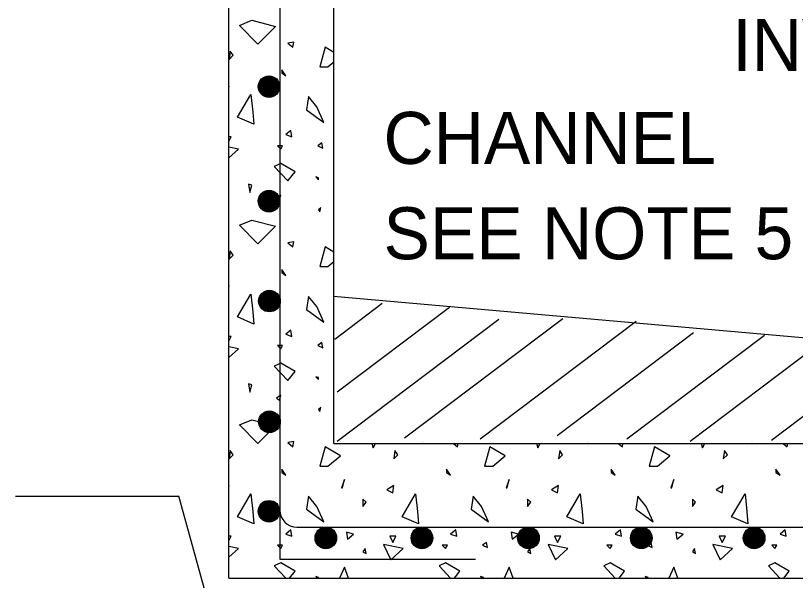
# Model space of a CAD drawing. Extents: x 5.8 to 18, y -5.2 to 5.4.
# Drawn here: x 11.214 to 12.113, y -2.201 to -1.55 of the extents above; entities that cross this region are included whole.
import ezdxf

# ---------------------------------------------------------------- set-up
doc = ezdxf.new("R2010")
doc.units = 0
for name, color, linetype in [('DETL-DIMS', 7, 'Continuous'), ('DETL-LINE', 7, 'Continuous'), ('DETL-NOTE', 7, 'Continuous'), ('DETL-PATT', 7, 'Continuous')]:
    doc.layers.add(name, color=color, linetype=linetype)

msp = doc.modelspace()

# ---------------------------------------------------------------- linework, layer by layer
at = {"layer": 'DETL-DIMS'}
for p in [(11.21361, -2.10408), (11.46459, -2.33018)]:
    msp.add_line(p, (11.40182, -2.10408), dxfattribs=at)
at = {"layer": 'DETL-LINE'}
for p, q in [((11.45961, -2.19861), (11.45961, -0.69269)), ((11.5809, -2.04328), (11.5809, -0.81414)), ((11.51843, -1.37418), (11.51843, -2.1203)), ((12.51612, -1.95637), (11.58024, -1.87386)), ((11.5809, -2.04328), (12.51612, -2.04328)), ((11.51843, -2.1203), (11.51843, -2.17673)), ((11.53804, -2.1399), (12.55565, -2.1399)), ((11.51843, -2.17673), (11.744, -2.17673)), ((11.45961, -2.19861), (12.646, -2.19861))]:
    msp.add_line(p, q, dxfattribs=at)
for centre, radius in [((11.50597, -1.63175), 0.01247), ((11.50586, -1.63164), 0.01163), ((11.50474, -1.63164), 0.01009), ((11.506, -1.63194), 0.01122), ((11.50633, -1.63247), 0.011), ((11.50627, -1.63207), 0.01024), ((11.50515, -1.63115), 0.00834), ((11.50655, -1.63213), 0.00969), ((11.50662, -1.63241), 0.00918), ((11.50496, -1.63213), 0.00724), ((11.50676, -1.63254), 0.00876), ((11.50662, -1.63276), 0.00835), ((11.50433, -1.63254), 0.00578), ((11.50684, -1.63276), 0.00814), ((11.50668, -1.63262), 0.00786), ((11.50704, -1.63282), 0.00751), ((11.50711, -1.63268), 0.00704), ((11.50717, -1.6326), 0.00655), ((11.50529, -1.63227), 0.00467), ((11.50717, -1.63247), 0.006), ((11.50725, -1.63262), 0.00565), ((11.50725, -1.63268), 0.0051), ((11.50747, -1.63311), 0.00488), ((11.50758, -1.63317), 0.00445), ((11.50758, -1.63305), 0.0039), ((11.50774, -1.63296), 0.00377), ((11.50774, -1.63331), 0.00347), ((11.50788, -1.63303), 0.00333), ((11.50794, -1.63311), 0.00285), ((11.50774, -1.6329), 0.00238), ((11.50802, -1.63319), 0.00212), ((11.50809, -1.63317), 0.00175), ((11.50823, -1.63325), 0.00133), ((11.50823, -1.63311), 0.00118), ((11.50864, -1.63317), 0.00148), ((11.50821, -1.63311), 0.000769), ((11.50807, -1.63311), 0.000362), ((11.50837, -1.63311), 0.00023), ((11.50597, -1.76383), 0.01247), ((11.50586, -1.76372), 0.01163), ((11.50474, -1.76372), 0.01009), ((11.506, -1.76402), 0.01122), ((11.50633, -1.76454), 0.011), ((11.50627, -1.76415), 0.01024), ((11.50515, -1.76323), 0.00834), ((11.50655, -1.76421), 0.00969), ((11.50662, -1.76449), 0.00918), ((11.50496, -1.76421), 0.00724), ((11.50676, -1.76462), 0.00876), ((11.50662, -1.76484), 0.00835), ((11.50433, -1.76462), 0.00578), ((11.50684, -1.76484), 0.00814), ((11.50668, -1.7647), 0.00786), ((11.50704, -1.7649), 0.00751), ((11.50711, -1.76476), 0.00704), ((11.50717, -1.76468), 0.00655), ((11.50529, -1.76435), 0.00467), ((11.50717, -1.76454), 0.006), ((11.50725, -1.7647), 0.00565), ((11.50725, -1.76476), 0.0051), ((11.50747, -1.76519), 0.00488), ((11.50758, -1.76525), 0.00445), ((11.50758, -1.76513), 0.0039), ((11.50774, -1.76503), 0.00377), ((11.50774, -1.76539), 0.00347), ((11.50788, -1.76511), 0.00333), ((11.50794, -1.76519), 0.00285), ((11.50774, -1.76498), 0.00238), ((11.50802, -1.76527), 0.00212), ((11.50809, -1.76525), 0.00175), ((11.50823, -1.76533), 0.00133), ((11.50823, -1.76519), 0.00118), ((11.50864, -1.76525), 0.00148), ((11.50821, -1.76519), 0.000769), ((11.50807, -1.76519), 0.000362), ((11.50837, -1.76519), 0.00023), ((11.50644, -1.87909), 0.01247), ((11.50633, -1.87898), 0.01163), ((11.50522, -1.87898), 0.01009), ((11.50647, -1.87928), 0.01122), ((11.5068, -1.87981), 0.011), ((11.50675, -1.87941), 0.01024), ((11.50563, -1.87849), 0.00834), ((11.50702, -1.87947), 0.00969), ((11.5071, -1.87975), 0.00918), ((11.50724, -1.87988), 0.00876), ((11.50543, -1.87947), 0.00724), ((11.5071, -1.8801), 0.00835), ((11.5048, -1.87988), 0.00578), ((11.50731, -1.8801), 0.00814), ((11.50716, -1.87996), 0.00786), ((11.50751, -1.88016), 0.00751), ((11.50759, -1.88002), 0.00704), ((11.50576, -1.87961), 0.00467), ((11.50765, -1.87994), 0.00655), ((11.50765, -1.87981), 0.006), ((11.50773, -1.87996), 0.00565), ((11.50773, -1.88002), 0.0051), ((11.50794, -1.88045), 0.00488), ((11.50806, -1.88051), 0.00445), ((11.50806, -1.88039), 0.0039), ((11.50822, -1.8803), 0.00377), ((11.50822, -1.88065), 0.00347), ((11.50835, -1.88037), 0.00333), ((11.50841, -1.88045), 0.00285), ((11.50822, -1.88024), 0.00238), ((11.50849, -1.88053), 0.00212), ((11.50857, -1.88051), 0.00175), ((11.50871, -1.88059), 0.00133), ((11.50871, -1.88045), 0.00118), ((11.50912, -1.88051), 0.00148), ((11.50869, -1.88045), 0.000769), ((11.50855, -1.88045), 0.000362), ((11.50884, -1.88045), 0.00023), ((11.50644, -2.01834), 0.01247), ((11.50633, -2.01824), 0.01163), ((11.50522, -2.01824), 0.01009), ((11.50647, -2.01853), 0.01122), ((11.5068, -2.01906), 0.011), ((11.50675, -2.01867), 0.01024), ((11.50563, -2.01775), 0.00834), ((11.50702, -2.01873), 0.00969), ((11.5071, -2.019), 0.00918), ((11.50543, -2.01873), 0.00724), ((11.50724, -2.01914), 0.00876), ((11.5071, -2.01935), 0.00835), ((11.5048, -2.01914), 0.00578), ((11.50731, -2.01935), 0.00814), ((11.50716, -2.01922), 0.00786), ((11.50751, -2.01941), 0.00751), ((11.50759, -2.01928), 0.00704), ((11.50576, -2.01886), 0.00467), ((11.50765, -2.0192), 0.00655), ((11.50765, -2.01906), 0.006), ((11.50773, -2.01922), 0.00565), ((11.50773, -2.01928), 0.0051), ((11.50794, -2.01971), 0.00488), ((11.50806, -2.01977), 0.00445), ((11.50806, -2.01965), 0.0039), ((11.50822, -2.01955), 0.00377), ((11.50822, -2.0199), 0.00347), ((11.50835, -2.01963), 0.00333), ((11.50841, -2.01971), 0.00285), ((11.50822, -2.01949), 0.00238), ((11.50849, -2.01979), 0.00212), ((11.50857, -2.01977), 0.00175), ((11.50871, -2.01985), 0.00133), ((11.50871, -2.01971), 0.00118), ((11.50912, -2.01977), 0.00148), ((11.50869, -2.01971), 0.000769), ((11.50855, -2.01971), 0.000362), ((11.50884, -2.01971), 0.00023), ((11.50597, -2.12159), 0.01247), ((11.50586, -2.12149), 0.01163), ((11.50474, -2.12149), 0.01009), ((11.506, -2.12178), 0.01122), ((11.50633, -2.12231), 0.011), ((11.50627, -2.12192), 0.01024), ((11.50515, -2.121), 0.00834), ((11.50655, -2.12198), 0.00969), ((11.50662, -2.12225), 0.00918), ((11.50676, -2.12239), 0.00876), ((11.50496, -2.12198), 0.00724), ((11.50662, -2.1226), 0.00835), ((11.50433, -2.12239), 0.00578), ((11.50684, -2.1226), 0.00814), ((11.50668, -2.12247), 0.00786), ((11.50704, -2.12266), 0.00751), ((11.50711, -2.12252), 0.00704), ((11.50717, -2.12245), 0.00655), ((11.50529, -2.12211), 0.00467), ((11.50717, -2.12231), 0.006), ((11.50725, -2.12247), 0.00565), ((11.50725, -2.12252), 0.0051), ((11.50747, -2.12296), 0.00488), ((11.50758, -2.12302), 0.00445), ((11.50758, -2.1229), 0.0039), ((11.50774, -2.1228), 0.00377), ((11.50774, -2.12315), 0.00347), ((11.50788, -2.12288), 0.00333), ((11.50794, -2.12296), 0.00285), ((11.50774, -2.12274), 0.00238), ((11.50802, -2.12303), 0.00212), ((11.50809, -2.12302), 0.00175), ((11.50823, -2.12309), 0.00133), ((11.50823, -2.12296), 0.00118), ((11.50864, -2.12302), 0.00148), ((11.50821, -2.12296), 0.000769), ((11.50807, -2.12296), 0.000362), ((11.50837, -2.12296), 0.00023), ((11.57149, -2.15237), 0.01247), ((11.57138, -2.15227), 0.01163), ((11.68235, -2.15237), 0.01247), ((11.68225, -2.15227), 0.01163), ((11.80525, -2.15237), 0.01247), ((11.80515, -2.15227), 0.01163), ((11.93541, -2.15237), 0.01247), ((11.93531, -2.15227), 0.01163), ((12.06557, -2.15237), 0.01247), ((12.06546, -2.15227), 0.01163), ((11.57027, -2.15227), 0.01009), ((11.57152, -2.15256), 0.01122), ((11.57185, -2.15309), 0.011), ((11.5718, -2.1527), 0.01024), ((11.57068, -2.15178), 0.00834), ((11.57207, -2.15276), 0.00969), ((11.57215, -2.15303), 0.00918), ((11.57048, -2.15276), 0.00724), ((11.57229, -2.15317), 0.00876), ((11.57215, -2.15338), 0.00835), ((11.56985, -2.15317), 0.00578), ((11.57236, -2.15338), 0.00814), ((11.57221, -2.15325), 0.00786), ((11.57256, -2.15344), 0.00751), ((11.57264, -2.1533), 0.00704), ((11.57081, -2.15289), 0.00467), ((11.5727, -2.15323), 0.00655), ((11.5727, -2.15309), 0.006), ((11.57278, -2.15325), 0.00565), ((11.57278, -2.1533), 0.0051), ((11.57299, -2.15374), 0.00488), ((11.57311, -2.15379), 0.00445), ((11.57311, -2.15368), 0.0039), ((11.57327, -2.15358), 0.00377), ((11.68113, -2.15227), 0.01009), ((11.68238, -2.15256), 0.01122), ((11.68272, -2.15309), 0.011), ((11.68266, -2.1527), 0.01024), ((11.68154, -2.15178), 0.00834), ((11.68293, -2.15276), 0.00969), ((11.68301, -2.15303), 0.00918), ((11.68134, -2.15276), 0.00724), ((11.68315, -2.15317), 0.00876), ((11.68301, -2.15338), 0.00835), ((11.68072, -2.15317), 0.00578), ((11.68323, -2.15338), 0.00814), ((11.68307, -2.15325), 0.00786), ((11.68342, -2.15344), 0.00751), ((11.6835, -2.1533), 0.00704), ((11.68356, -2.15323), 0.00655), ((11.68168, -2.15289), 0.00467), ((11.68356, -2.15309), 0.006), ((11.68364, -2.15325), 0.00565), ((11.68364, -2.1533), 0.0051), ((11.68385, -2.15374), 0.00488), ((11.68397, -2.15379), 0.00445), ((11.68397, -2.15368), 0.0039), ((11.68413, -2.15358), 0.00377), ((11.80403, -2.15227), 0.01009), ((11.80529, -2.15256), 0.01122), ((11.80562, -2.15309), 0.011), ((11.80556, -2.1527), 0.01024), ((11.80444, -2.15178), 0.00834), ((11.80583, -2.15276), 0.00969), ((11.80591, -2.15303), 0.00918), ((11.80425, -2.15276), 0.00724), ((11.80605, -2.15317), 0.00876), ((11.80591, -2.15338), 0.00835), ((11.80362, -2.15317), 0.00578), ((11.80613, -2.15338), 0.00814), ((11.80597, -2.15325), 0.00786), ((11.80632, -2.15344), 0.00751), ((11.8064, -2.1533), 0.00704), ((11.80646, -2.15323), 0.00655), ((11.80458, -2.15289), 0.00467), ((11.80646, -2.15309), 0.006), ((11.80654, -2.15325), 0.00565), ((11.80654, -2.1533), 0.0051), ((11.80676, -2.15374), 0.00488), ((11.80687, -2.15379), 0.00445), ((11.80687, -2.15368), 0.0039), ((11.80703, -2.15358), 0.00377), ((11.93419, -2.15227), 0.01009), ((11.93544, -2.15256), 0.01122), ((11.93578, -2.15309), 0.011), ((11.93572, -2.1527), 0.01024), ((11.9346, -2.15178), 0.00834), ((11.93599, -2.15276), 0.00969), ((11.93607, -2.15303), 0.00918), ((11.9344, -2.15276), 0.00724), ((11.93621, -2.15317), 0.00876), ((11.93607, -2.15338), 0.00835), ((11.93378, -2.15317), 0.00578), ((11.93629, -2.15338), 0.00814), ((11.93613, -2.15325), 0.00786), ((11.93648, -2.15344), 0.00751), ((11.93656, -2.1533), 0.00704), ((11.93474, -2.15289), 0.00467), ((11.93662, -2.15323), 0.00655), ((11.93662, -2.15309), 0.006), ((11.9367, -2.15325), 0.00565), ((11.9367, -2.1533), 0.0051), ((11.93691, -2.15374), 0.00488), ((11.93703, -2.15379), 0.00445), ((11.93703, -2.15368), 0.0039), ((11.93719, -2.15358), 0.00377), ((12.06434, -2.15227), 0.01009), ((12.0656, -2.15256), 0.01122), ((12.06593, -2.15309), 0.011), ((12.06587, -2.1527), 0.01024), ((12.06476, -2.15178), 0.00834), ((12.06615, -2.15276), 0.00969), ((12.06623, -2.15303), 0.00918), ((12.06456, -2.15276), 0.00724), ((12.06636, -2.15317), 0.00876), ((12.06623, -2.15338), 0.00835), ((12.06393, -2.15317), 0.00578), ((12.06644, -2.15338), 0.00814), ((12.06629, -2.15325), 0.00786), ((12.06664, -2.15344), 0.00751), ((12.06672, -2.1533), 0.00704), ((12.06489, -2.15289), 0.00467), ((12.06678, -2.15323), 0.00655), ((12.06678, -2.15309), 0.006), ((12.06685, -2.15325), 0.00565), ((12.06685, -2.1533), 0.0051), ((12.06707, -2.15374), 0.00488), ((12.06719, -2.15379), 0.00445), ((12.06719, -2.15368), 0.0039), ((12.06734, -2.15358), 0.00377), ((11.57327, -2.15393), 0.00347), ((11.5734, -2.15366), 0.00333), ((11.57346, -2.15374), 0.00285), ((11.57327, -2.15352), 0.00238), ((11.57354, -2.15381), 0.00212), ((11.57362, -2.15379), 0.00175), ((11.57376, -2.15387), 0.00133), ((11.57376, -2.15374), 0.00118), ((11.57417, -2.15379), 0.00148), ((11.57374, -2.15374), 0.000769), ((11.5736, -2.15374), 0.000362), ((11.57389, -2.15374), 0.00023), ((11.68413, -2.15393), 0.00347), ((11.68427, -2.15366), 0.00333), ((11.68432, -2.15374), 0.00285), ((11.68413, -2.15352), 0.00238), ((11.6844, -2.15381), 0.00212), ((11.68448, -2.15379), 0.00175), ((11.68462, -2.15387), 0.00133), ((11.68462, -2.15374), 0.00118), ((11.68503, -2.15379), 0.00148), ((11.6846, -2.15374), 0.000769), ((11.68446, -2.15374), 0.000362), ((11.68476, -2.15374), 0.00023), ((11.80703, -2.15393), 0.00347), ((11.80717, -2.15366), 0.00333), ((11.80723, -2.15374), 0.00285), ((11.80703, -2.15352), 0.00238), ((11.80731, -2.15381), 0.00212), ((11.80738, -2.15379), 0.00175), ((11.80752, -2.15387), 0.00133), ((11.80752, -2.15374), 0.00118), ((11.80793, -2.15379), 0.00148), ((11.8075, -2.15374), 0.000769), ((11.80736, -2.15374), 0.000362), ((11.80766, -2.15374), 0.00023), ((11.93719, -2.15393), 0.00347), ((11.93732, -2.15366), 0.00333), ((11.93738, -2.15374), 0.00285), ((11.93719, -2.15352), 0.00238), ((11.93746, -2.15381), 0.00212), ((11.93754, -2.15379), 0.00175), ((11.93768, -2.15387), 0.00133), ((11.93768, -2.15374), 0.00118), ((11.93809, -2.15379), 0.00148), ((11.93766, -2.15374), 0.000769), ((11.93752, -2.15374), 0.000362), ((11.93781, -2.15374), 0.00023), ((12.06734, -2.15393), 0.00347), ((12.06748, -2.15366), 0.00333), ((12.06754, -2.15374), 0.00285), ((12.06734, -2.15352), 0.00238), ((12.06762, -2.15381), 0.00212), ((12.0677, -2.15379), 0.00175), ((12.06783, -2.15387), 0.00133), ((12.06783, -2.15374), 0.00118), ((12.06825, -2.15379), 0.00148), ((12.06781, -2.15374), 0.000769), ((12.06768, -2.15374), 0.000362), ((12.06797, -2.15374), 0.00023)]:
    msp.add_circle(centre, radius, dxfattribs=at)
msp.add_arc((11.53804, -2.1203), 0.01961, 180, 270, dxfattribs=at)
at = {"layer": 'DETL-PATT'}
for p, q in [((11.58176, -1.92312), (11.63663, -1.88171)), ((11.58439, -1.98394), (11.71412, -1.88602)), ((11.58439, -2.04081), (11.77098, -1.89994)), ((11.66239, -2.03681), (11.84475, -1.89916)), ((11.74965, -2.03814), (11.92965, -1.90226)), ((11.83824, -2.03418), (11.99549, -1.91547)), ((11.91886, -2.03814), (12.07737, -1.91849)), ((11.99161, -2.04081), (12.15286, -1.91908)), ((12.08545, -2.03947), (12.22898, -1.93116))]:
    msp.add_line(p, q, dxfattribs=at)
for points in [[(11.48612, -1.5552), (11.51349, -1.56226), (11.49318, -1.58261), (11.47173, -1.56116)], [(11.52761, -1.58147), (11.53357, -1.58626), (11.53467, -1.58034)], [(11.46125, -1.59081), (11.45984, -1.60037), (11.46467, -1.59559)], [(11.52055, -1.61226), (11.52055, -1.6159), (11.52537, -1.61932)], [(11.48725, -1.66108), (11.48839, -1.6752), (11.46945, -1.66704), (11.48498, -1.64077)], [(11.55133, -1.64332), (11.5491, -1.65857), (11.56914, -1.67296), (11.56094, -1.65516)], [(11.53129, -1.68226), (11.52537, -1.68708), (11.53243, -1.68963)], [(11.51576, -1.70006), (11.51945, -1.70375), (11.52169, -1.70006)], [(11.56208, -1.70006), (11.568, -1.70261), (11.56686, -1.69669)], [(11.51208, -1.72379), (11.52761, -1.74045), (11.53608, -1.72998), (11.51945, -1.72037)], [(11.56322, -1.73704), (11.5598, -1.7359), (11.56322, -1.73932)], [(11.48243, -1.7441), (11.48384, -1.75371), (11.48612, -1.74524)], [(11.51463, -1.76077), (11.51804, -1.76304), (11.51945, -1.75708)], [(11.56573, -1.77151), (11.56322, -1.77375), (11.56463, -1.7763)], [(11.48612, -1.78563), (11.51349, -1.79269), (11.49318, -1.813), (11.47173, -1.79155)], [(11.52761, -1.81186), (11.53357, -1.81669), (11.53467, -1.81073)], [(11.46125, -1.8212), (11.45984, -1.83081), (11.46467, -1.82598)], [(11.52055, -1.84265), (11.52055, -1.84634), (11.52537, -1.84971)], [(11.48725, -1.89151), (11.48839, -1.90563), (11.46945, -1.89743), (11.48498, -1.87116)], [(11.55133, -1.87371), (11.5491, -1.88896), (11.56914, -1.90335), (11.56094, -1.88555)], [(11.53129, -1.91269), (11.52537, -1.91747), (11.53243, -1.92002)], [(11.51576, -1.93045), (11.51945, -1.93414), (11.52169, -1.93045)], [(11.56208, -1.93045), (11.568, -1.933), (11.56686, -1.92708)], [(11.51208, -1.95418), (11.52761, -1.97085), (11.53608, -1.96037), (11.51945, -1.95081)], [(11.56322, -1.96743), (11.5598, -1.96634), (11.56322, -1.96971)], [(11.48243, -1.97449), (11.48384, -1.9841), (11.48612, -1.97563)], [(11.51463, -1.99116), (11.51804, -1.99343), (11.51945, -1.98751)], [(11.56573, -2.0019), (11.56322, -2.00414), (11.56463, -2.00669)], [(11.48612, -2.01602), (11.51349, -2.02308), (11.49318, -2.04339), (11.47173, -2.02194)], [(11.52761, -2.04226), (11.53357, -2.04708), (11.53467, -2.04116)], [(11.57392, -2.06967), (11.58831, -2.05751), (11.57055, -2.04708), (11.56463, -2.06967)], [(11.76396, -2.06967), (11.77835, -2.05751), (11.76055, -2.04708), (11.75463, -2.06967)], [(11.95396, -2.06967), (11.96839, -2.05751), (11.95059, -2.04708), (11.94467, -2.06967)], [(11.46125, -2.05159), (11.45984, -2.0612), (11.46467, -2.05637)], [(11.65129, -2.05159), (11.64988, -2.0612), (11.65467, -2.05637)], [(11.84133, -2.05159), (11.83992, -2.0612), (11.84471, -2.05637)], [(12.03133, -2.05159), (12.02992, -2.0612), (12.03475, -2.05637)], [(11.52055, -2.07304), (11.52055, -2.07673), (11.52537, -2.0801)], [(11.71059, -2.07304), (11.71059, -2.07673), (11.71537, -2.0801)], [(11.90063, -2.07304), (11.90063, -2.07673), (11.90541, -2.0801)], [(12.09063, -2.07304), (12.09063, -2.07673), (12.09545, -2.0801)], [(11.58945, -2.09449), (11.59059, -2.09449), (11.59286, -2.08492)], [(11.77949, -2.09449), (11.78063, -2.09449), (11.78286, -2.08492)], [(11.96949, -2.09449), (11.97063, -2.09449), (11.9729, -2.08492)], [(11.64169, -2.09677), (11.64875, -2.10045), (11.64988, -2.09198)], [(11.83173, -2.09677), (11.83878, -2.10045), (11.83992, -2.09198)], [(12.02173, -2.09677), (12.02878, -2.10045), (12.02992, -2.09198)], [(11.48725, -2.1219), (11.48839, -2.13602), (11.46945, -2.12783), (11.48498, -2.10155)], [(11.55133, -2.1041), (11.5491, -2.11935), (11.56914, -2.13375), (11.56094, -2.11598)], [(11.67725, -2.1219), (11.67839, -2.13602), (11.65949, -2.12783), (11.67502, -2.10155)], [(11.74137, -2.1041), (11.7391, -2.11935), (11.75914, -2.13375), (11.75098, -2.11598)], [(11.86729, -2.1219), (11.86843, -2.13602), (11.84949, -2.12783), (11.86502, -2.10155)], [(11.93137, -2.1041), (11.92914, -2.11935), (11.94918, -2.13375), (11.94098, -2.11598)], [(12.05733, -2.1219), (12.05843, -2.13602), (12.03953, -2.12783), (12.05506, -2.10155)], [(11.61431, -2.10751), (11.61431, -2.11598), (11.61796, -2.11116)], [(11.80431, -2.10751), (11.80431, -2.11598), (11.808, -2.11116)], [(11.99435, -2.10751), (11.99435, -2.11598), (11.99804, -2.11116)], [(11.53129, -2.14308), (11.52537, -2.14786), (11.53243, -2.15041)], [(11.59537, -2.14563), (11.59651, -2.15379), (11.60357, -2.14786)], [(11.72133, -2.14308), (11.71537, -2.14786), (11.72243, -2.15041)], [(11.78541, -2.14563), (11.78655, -2.15379), (11.79361, -2.14786)], [(11.91133, -2.14308), (11.90541, -2.14786), (11.91247, -2.15041)], [(11.97545, -2.14563), (11.97655, -2.15379), (11.98361, -2.14786)], [(12.10137, -2.14308), (12.09545, -2.14786), (12.10251, -2.15041)], [(11.56208, -2.16085), (11.568, -2.16339), (11.56686, -2.15747)], [(11.64537, -2.15041), (11.64875, -2.15747), (11.65243, -2.15041)], [(11.75208, -2.16085), (11.75804, -2.16339), (11.7569, -2.15747)], [(11.83537, -2.15041), (11.83878, -2.15747), (11.84243, -2.15041)], [(11.94212, -2.16085), (11.94804, -2.16339), (11.9469, -2.15747)], [(12.02541, -2.15041), (12.02878, -2.15747), (12.03247, -2.15041)], [(11.51576, -2.16085), (11.51945, -2.16453), (11.52169, -2.16085)], [(11.61431, -2.16822), (11.61796, -2.17045), (11.61686, -2.16453)], [(11.63804, -2.15975), (11.64651, -2.17751), (11.66063, -2.16453)], [(11.7058, -2.16085), (11.70945, -2.16453), (11.71173, -2.16085)], [(11.80431, -2.16822), (11.808, -2.17045), (11.80686, -2.16453)], [(11.82804, -2.15975), (11.83651, -2.17751), (11.85063, -2.16453)], [(11.8958, -2.16085), (11.89949, -2.16453), (11.90173, -2.16085)], [(11.99435, -2.16822), (11.99804, -2.17045), (11.9969, -2.16453)], [(12.01808, -2.15975), (12.02655, -2.17751), (12.04067, -2.16453)], [(12.08584, -2.16085), (12.08949, -2.16453), (12.09176, -2.16085)]]:
    msp.add_lwpolyline(points, close=True, dxfattribs=at)
for points in [[(11.5809, -1.59237), (11.57055, -1.58626), (11.56463, -1.60885), (11.57392, -1.60885), (11.5809, -1.60296)], [(11.45961, -1.63296), (11.45984, -1.63116), (11.45961, -1.63132)], [(11.45961, -1.69496), (11.46239, -1.68963), (11.45961, -1.68963)], [(11.45961, -1.71383), (11.47059, -1.70375), (11.45961, -1.70139)], [(11.5809, -1.82277), (11.57055, -1.81669), (11.56463, -1.83928), (11.57392, -1.83928), (11.5809, -1.83335)], [(11.45961, -1.86335), (11.45984, -1.86155), (11.45961, -1.86171)], [(11.45961, -1.92535), (11.46239, -1.92002), (11.45961, -1.92002)], [(11.45961, -1.94422), (11.47059, -1.93414), (11.45961, -1.93179)], [(11.62459, -2.04328), (11.62616, -2.04822), (11.62875, -2.04328)], [(11.68333, -2.04328), (11.68322, -2.04339), (11.68306, -2.04328)], [(11.71886, -2.04328), (11.72357, -2.04708), (11.72431, -2.04328)], [(11.81463, -2.04328), (11.8162, -2.04822), (11.81875, -2.04328)], [(11.87337, -2.04328), (11.87322, -2.04339), (11.8731, -2.04328)], [(11.9089, -2.04328), (11.91361, -2.04708), (11.91431, -2.04328)], [(12.00463, -2.04328), (12.0062, -2.04822), (12.00878, -2.04328)], [(12.06337, -2.04328), (12.06325, -2.04339), (12.0631, -2.04328)], [(12.09894, -2.04328), (12.10361, -2.04708), (12.10435, -2.04328)], [(11.45961, -2.09375), (11.45984, -2.09198), (11.45961, -2.0921)], [(11.45961, -2.15575), (11.46239, -2.15041), (11.45961, -2.15041)], [(11.45961, -2.17461), (11.47059, -2.16453), (11.45961, -2.16222)], [(11.52976, -2.19861), (11.53608, -2.19081), (11.51945, -2.1812), (11.51208, -2.18457), (11.52518, -2.19861)], [(11.59773, -2.19861), (11.59286, -2.18598), (11.58729, -2.19861)], [(11.7198, -2.19861), (11.72612, -2.19081), (11.70945, -2.1812), (11.70212, -2.18457), (11.71518, -2.19861)], [(11.78773, -2.19861), (11.78286, -2.18598), (11.77733, -2.19861)], [(11.9098, -2.19861), (11.91616, -2.19081), (11.89949, -2.1812), (11.89216, -2.18457), (11.90522, -2.19861)], [(11.97776, -2.19861), (11.9729, -2.18598), (11.96733, -2.19861)], [(12.09984, -2.19861), (12.10616, -2.19081), (12.08949, -2.1812), (12.08216, -2.18457), (12.09525, -2.19861)], [(11.56322, -2.19861), (11.56322, -2.19786), (11.5598, -2.19673), (11.56169, -2.19861)], [(11.75322, -2.19861), (11.75322, -2.19786), (11.74984, -2.19673), (11.75173, -2.19861)], [(11.94325, -2.19861), (11.94325, -2.19786), (11.93984, -2.19673), (11.94173, -2.19861)]]:
    msp.add_lwpolyline(points, dxfattribs=at)

# ---------------------------------------------------------------- texts
at = {"layer": 'DETL-NOTE'}
for s, p in [('INVERT', (12.04039, -1.61371)), ('CHANNEL', (11.638, -1.72088)), ('SEE NOTE 5', (11.638, -1.83088))]:
    msp.add_text(s, height=0.06, dxfattribs=at).set_placement(p)

doc.saveas('drawing.dxf')
